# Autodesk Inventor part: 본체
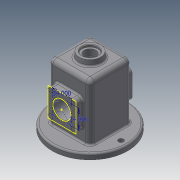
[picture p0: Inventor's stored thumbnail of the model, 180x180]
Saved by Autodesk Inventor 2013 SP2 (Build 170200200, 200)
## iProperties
Created: 2021-08
Part Number: 본체
Material: Generic
Document SubType Name: Modeling
Designer: kumcom8
Density: 1 g/cm^3
Author: kumcom8
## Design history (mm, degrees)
sketch "스케치1"
  geometry: C1 r 1701.8 at (0, 0); 1 further point
  constraints: 1 centre point, 1 coincident
  dimensions: "d0" = 3403.6 diameter of C1
extrude "돌출1" new body sketch "스케치1" distance "d1" = 254; taper "d2" = 0 deg
sketch "스케치2"
  geometry: L1 (-939.8, -939.8)-(939.8, -939.8); L2 (939.8, -939.8)-(939.8, 939.8); L3 (939.8, 939.8)-(-939.8, 939.8); L4 (-939.8, 939.8)-(-939.8, -939.8); L5 (-939.8, -939.8)-(939.8, 939.8); L6 (939.8, -939.8)-(-939.8, 939.8); C1 r 1701.8 at (0, 0) reference
  constraints: 12 end point, 2 midpoint, 2 parallel, 1 horizontal, 1 perpendicular
  dimensions: "d3" = 1879.6 distance of L3.end L2.end; "d4" = 1879.6 distance of L1.end L2.end
extrude "돌출2" join sketch "스케치2" distance "d5" = 2540; taper "d6" = 0 deg
sketch "스케치3"
  geometry: L1 (-635, 762)-(635, 762); L2 (635, 762)-(635, 2032); L3 (635, 2032)-(-635, 2032); L4 (-635, 2032)-(-635, 762); L5 (-635, 762)-(635, 2032); L6 (635, 762)-(-635, 2032); L7 (-1701.8, 0)-(1701.8, 0) reference; 3 further points
  constraints: 12 end point, 3 midpoint, 2 parallel, 1 horizontal, 1 perpendicular, 1 vertical alignment
  dimensions: "d7" = 1270 distance of L3.end L2.end; "d8" = 1270 distance of L2.end L1.end; "d9" = 1397 distance from line of L7 point (0, 1397)
extrude "돌출3" join sketch "스케치3" stored distance "d10" = 2540; taper "d11" = 0 deg
sketch "스케치4"
  geometry: C1 r 508 at (0, 0); 1 further point
  constraints: 1 centre point, 1 coincident
  dimensions: "d12" = 1016 diameter of C1
extrude "돌출4" join sketch "스케치4" distance "d13" = 254; taper "d14" = 0 deg
feature "면 기울기1" dims angle "d15" = 6 deg
sketch "스케치5"
  geometry: L1 (-1701.8, 0)-(1701.8, 0) reference; L2 (-939.8, 254)-(-939.8, 2794) reference; C1 r 406.4 at (0, 1397); 1 further point
  constraints: 1 centre point
  dimensions: "d16" = 812.8 diameter of C1; "d17" = 1397 distance from line of L1 C1.centre; "d18" = 939.8 distance from line of L2 C1.centre
extrude "돌출5" cut sketch "스케치5" distance "d19" = 3475.0375; taper "d20" = 0 deg
sketch "스케치6"
  geometry: C1 r 481.304 at (0, 0) reference; C2 r 266.7 at (0, 0)
  constraints: 1 centre point, 1 coincident
  dimensions: "d21" = 533.4 diameter of C2
extrude "돌출6" cut sketch "스케치6" distance "d22" = 1828.8; taper "d23" = 0 deg
sketch "스케치7"
  geometry: C1 r 266.7 at (0, 0) reference; C2 r 481.304 at (0, 0) reference; C3 r 355.6 at (0, 0)
  constraints: 1 centre point, 1 coincident
  dimensions: "d24" = 711.2 diameter of C3
extrude "돌출7" cut sketch "스케치7" distance "d25" = 101.6; taper "d26" = 0 deg
sketch "스케치8"
  geometry: L1 (812.8, 812.8)-(-812.8, 812.8); L2 (-812.8, 812.8)-(-812.8, -812.8); L3 (-812.8, -812.8)-(812.8, -812.8); L4 (812.8, -812.8)-(812.8, 812.8); L5 (812.8, 812.8)-(-812.8, -812.8); L6 (-812.8, 812.8)-(812.8, -812.8); C1 r 1701.8 at (0, 0) reference
  constraints: 12 end point, 2 midpoint, 2 parallel, 1 horizontal, 1 perpendicular
  dimensions: "d27" = 1625.6 distance of L3.end L2.end; "d28" = 1625.6 distance of L1.end L2.end
extrude "돌출8" cut sketch "스케치8" distance "d29" = 2667; taper "d30" = 0 deg
sketch "스케치9"
  geometry: C1 r 406.4 at (812.8, 1397) reference; C2 r 635 at (812.8, 1397); 1 further point
  constraints: 1 centre point, 1 coincident
  dimensions: "d31" = 1270 diameter of C2
extrude "돌출9" join sketch "스케치9" distance "d32" = 177.8; taper "d33" = 0 deg
feature "면 기울기2" dims angle "d34" = 20 deg
feature "면 기울기3" dims angle "d35" = 20 deg
sketch "스케치10"
  geometry: L1 (-431.8, 965.2)-(431.8, 965.2); L2 (431.8, 965.2)-(431.8, 1828.8); L3 (431.8, 1828.8)-(-431.8, 1828.8); L4 (-431.8, 1828.8)-(-431.8, 965.2); L5 (-431.8, 965.2)-(431.8, 1828.8); L6 (431.8, 965.2)-(-431.8, 1828.8); L7 (-635, 762)-(635, 762) reference; L8 (635, 762)-(635, 2032) reference; L9 (635, 2032)-(-635, 2032) reference; L10 (-635, 2032)-(-635, 762) reference; C1 r 406.4 at (0, 1397) reference; 5 further points
  constraints: 12 end point, 4 coincident, 2 midpoint, 2 parallel, 1 horizontal, 1 perpendicular
  dimensions: "d36" = 863.6 distance of L3.end L2.end; "d37" = 863.6 distance of L1.end L2.end
sketch "스케치11"
  geometry: C1 r 1701.8 at (0, 0) reference; C2 r 114.3 at (-1397, 0); C3 r 114.3 at (1397, 0); A1 r 1397 centre (0, 0) between (-1397, 0) and (1397, 0)
  constraints: 3 centre point, 2 horizontal alignment, 2 point on circle, 1 coincident
  dimensions: "d38" = 2794 diameter of A1; "d39" = 228.6 diameter of C2; "d40" = 228.6 diameter of C3
extrude "돌출10" cut sketch "스케치11" stored distance "d41" = 177.8; taper "d42" = 0 deg
fillet "모깎기1" dims "d43" = 203.2
fillet "모깎기2" dims "d44" = 203.2
fillet "모깎기3" dims "d45" = 76.2
chamfer "모따기1" distance "d46" = 25.4; stored, may be unused: second distance "d47" = 3.175, angle "d48" = 45 deg
node "작업 평면1"
sketch "스케치12"
  geometry: L1 (-939.8, 2590.8)-(-939.8, 330.2) reference; L2 (481.304, 3048)-(-481.304, 3048) reference; 2 further points
  constraints: 1 other
  dimensions: "d57" = 939.8 distance from line of L1 point (0, 2336.8); "d58" = 711.2 distance from line of point (0, 2336.8) L2
feature "엠보싱1" sketch "스케치12" dims "d1" = 254, "d2" = 0, "d7" = 1270, "d8" = 1270, "d9" = 1397, "d59" = 12.7, "d60" = 0
node "솔리드1"
mirror "대칭1"
other parameters: "d56" = 0
